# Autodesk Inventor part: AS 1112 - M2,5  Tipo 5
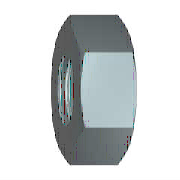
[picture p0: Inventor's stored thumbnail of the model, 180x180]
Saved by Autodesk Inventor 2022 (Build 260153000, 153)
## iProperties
Created: 2021-02
Part Number: AS 1112 - M2,5  Tipo 5
Material: Acciaio, Dolce
Description: Dadi esagonali metrici ISO, inclusi dadi sottili, dadi con intaglio e dadi a corona
Document SubType Name: Modeling
Standard: AS 1112
Designer: admin
Standards Organization: AS
Language: it-IT
Size Designation: M2,5  Tipo 5
Categories: <MemberInstance><Categories><Category DisplayName="Elementi di fissaggio" InternalName="e4da775c-781d-43d5-af7c-5136215cf5a6" Mnemonic="FSTN"><Category DisplayN
Density: 7.85 g/cm^3
Appearance: Semilucidato
IsCustomPart: 0
Author: admin
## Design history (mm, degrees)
sketch "Schizzo1"
  geometry: L1 (-2.887, 0)-(-1.443, 2.5); L2 (-1.443, 2.5)-(1.443, 2.5); L3 (1.443, 2.5)-(2.887, 0); L4 (2.887, 0)-(1.443, -2.5); L5 (1.443, -2.5)-(-1.443, -2.5); L6 (-1.443, -2.5)-(-2.887, 0); 2 further points
  constraints: 12 end point, 1 coincident, 1 horizontal, 11 other
  dimensions: "d0" = 5.7735 distance of L3.end L1.start (= 1.1547 x SW)
extrude "Corpo" new body sketch "Schizzo1" distance "d1" = 2 (= KOH); taper "d2" = 0 deg
sketch "Schizzo2"
  geometry: L1 (0, 1.443)-(0, 2.887) reference; L2 (0, 2.887)-(2, 2.887) reference; L3 (2, 1.443)-(2, 2.887) reference; L4 (-0.4, 0)-(2.4, 0) reference; L5 (0.223, 2.887)-(0, 2.5); L6 (1.777, 2.887)-(2, 2.5)
  constraints: 4 end point, 4 point on line
  dimensions: "d3" = 30 deg angle of L1 L5 (= ANG1); "d4" = 30 deg angle of L3 L6 (= ANG2); "d5" = 5 diameter of L5.end L4 (= SW0); "d6" = 5 diameter of L6.end L4 (= SW01)
revolve "Smusso1" sketch "Schizzo2" stored, may be unused: angle "d7" = 90 deg
sketch "Schizzo3"
  geometry: A1 r 2.5 centre (0, 0) between (-1.25, -2.165) and (1.25, -2.165) reference; 1 further point
  constraints: 1 coincident
hole "Filettatura" sketch "Schizzo3" at (0, 0) diameter "d25" = 2.013; stored, may be unused: countersink angle "d29" = 82 deg, drill point angle "d31" = 118 deg; dims "d26" = 6, "d27" = 4, "d28" = 2, "d30" = 8
workaxis "Work Axis1"
workplane "Work Plane1"
body "Solid1"
chamfer "Smusso2" distance "d8" = 0.24357 (= -0.5 x GD1 + 0.5 x NND); stored, may be unused: angle "d9" = 30 deg, second distance "d40" = 0.24357 (= -0.5 x GD1 + 0.5 x NND)
chamfer "Smusso3" distance "d10" = 0.24357 (= -0.5 x GD1 + 0.5 x NND); stored, may be unused: angle "d11" = 30 deg, second distance "d41" = 0.24357 (= -0.5 x GD1 + 0.5 x NND)
other parameters: "ANG1" = 30 deg [user parameter; used in 1 equation term], "ANG2" = 30 deg [user parameter; used in 1 equation term], "NND" = 2.5 [user parameter; used in 4 equation terms], "KOH" = 2 [user parameter; used in 1 equation term], "SW" = 5 [user parameter; used in 4 equation terms], "SW0" = 5 (= SW) [user parameter; used in 1 equation term], "SW01" = 5 (= SW) [user parameter; used in 1 equation term], "GD1" = 2.01286 (computed from THREADDIA, PTC, TOA) [user parameter; used in 4 equation terms], "d13" = 0, "d14" = 0, "d39" = 0, "d42" = 0, "GUL" = 0.24357 (= 0.541266 x PTC) [user parameter], "TPU" = 22.22222 (computed from PTC) [user parameter], "WFT" = 0 [user parameter], "THREADDIA" = 2.5 [user parameter; used in 1 equation term], "TOA" = 30 deg [user parameter; used in 1 equation term], "PTC" = 0.45 [user parameter; used in 4 equation terms], "E0" = 5.775 (= 1.155 x SW) [user parameter], "GAL" = 0.24357 (= 0.541266 x PTC) [user parameter]
